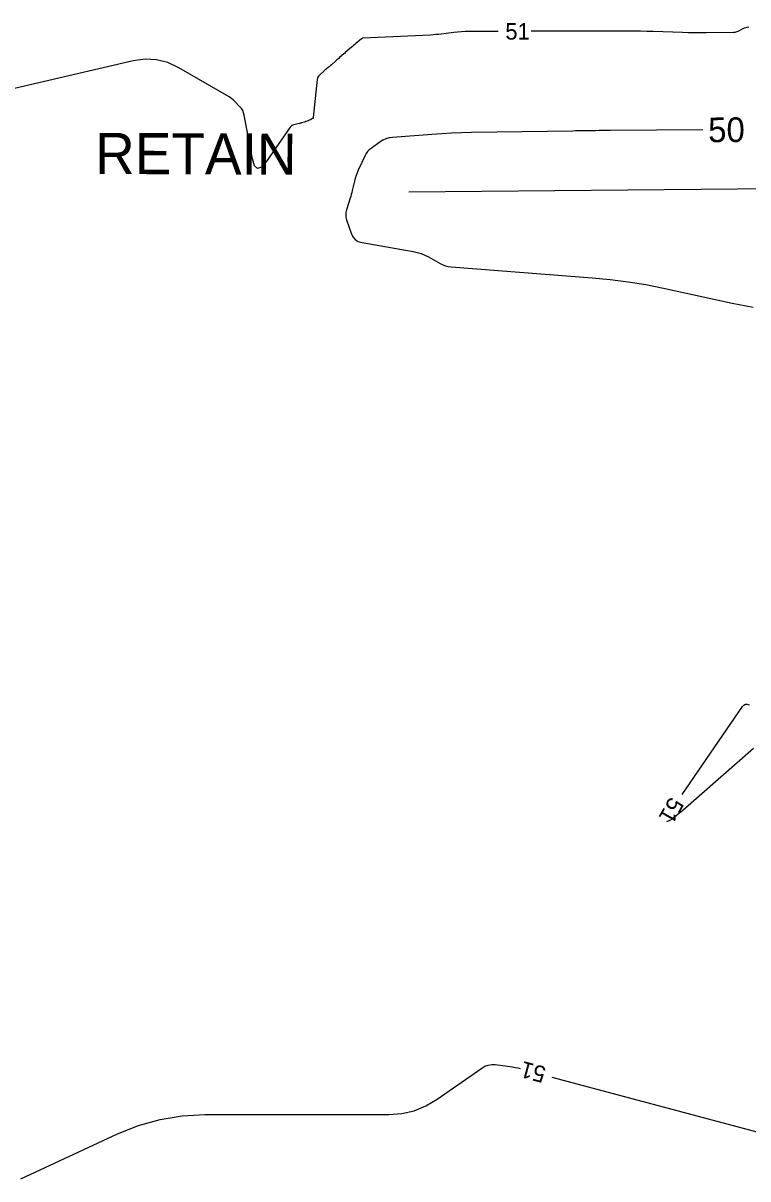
# Model space of a CAD drawing. Extents: x 2384780 to 2405861, y 547869 to 573706.
# Drawn here: x 2391543.5 to 2391631.6, y 552463.3 to 552603.9 of the extents above; entities that cross this region are included whole.
import ezdxf

# ---------------------------------------------------------------- set-up
doc = ezdxf.new("R2010")
doc.units = 0
for name, color, linetype in [('Old_Level_5', 7, 'Continuous'), ('Old_Level_60', 7, 'Continuous'), ('Old_Level_61', 7, 'Continuous')]:
    doc.layers.add(name, color=color, linetype=linetype)

msp = doc.modelspace()

# ---------------------------------------------------------------- linework, layer by layer
at = {"layer": 'Old_Level_5'}
msp.add_line((2391590.4, 552583.40025), (2391754.736, 552584.94575), dxfattribs=at)
at = {"layer": 'Old_Level_60'}
for points in [[(2391631.75, 552603.4255), (2391631.55325, 552603.40975), (2391631.3625, 552603.372), (2391631.17725, 552603.312), (2391630.998, 552603.22975), (2391630.4215, 552602.925), (2391630.296, 552602.86775), (2391630.1665, 552602.8265), (2391630.03275, 552602.801), (2391629.89525, 552602.79175), (2391626.55125, 552602.7595), (2391625.83475, 552602.75625), (2391625.1185, 552602.761), (2391624.40225, 552602.77325), (2391623.686, 552602.79325), (2391620.101, 552602.9125), (2391619.33275, 552602.93475), (2391618.56425, 552602.95025), (2391617.79575, 552602.95875), (2391617.02725, 552602.96075), (2391605.2555, 552602.938)], [(2391601.2555, 552602.93025), (2391597.7095, 552602.9235), (2391597.24275, 552602.915), (2391596.77675, 552602.892), (2391596.312, 552602.854), (2391595.848, 552602.8015), (2391594.33425, 552602.60525), (2391594.0095, 552602.5665), (2391593.68425, 552602.53425), (2391593.35825, 552602.509), (2391593.03175, 552602.49025), (2391584.76875, 552602.10075), (2391584.75225, 552602.09875), (2391584.7365, 552602.09425), (2391584.722, 552602.08725), (2391584.70825, 552602.07775), (2391584.665, 552602.043), (2391584.656, 552602.0355), (2391584.64675, 552602.028), (2391584.6375, 552602.0205), (2391584.62825, 552602.01275), (2391583.94775, 552601.44925), (2391583.80225, 552601.32825), (2391583.657, 552601.20675), (2391583.51225, 552601.0845), (2391583.368, 552600.962), (2391582.89425, 552600.55825), (2391582.793, 552600.4715), (2391582.692, 552600.3845), (2391582.59125, 552600.29725), (2391582.49075, 552600.2095), (2391581.96525, 552599.74875), (2391581.85275, 552599.65), (2391581.74075, 552599.55075), (2391581.62875, 552599.45125), (2391581.51725, 552599.3515), (2391580.9545, 552598.84675), (2391580.871, 552598.7735), (2391580.786, 552598.70225), (2391580.69925, 552598.63325), (2391580.61075, 552598.566), (2391580.31975, 552598.3495), (2391580.258, 552598.3025), (2391580.1975, 552598.2535), (2391580.1385, 552598.20325), (2391580.081, 552598.151), (2391579.5115, 552597.62275), (2391579.4025, 552597.503), (2391579.32, 552597.37), (2391579.26325, 552597.224), (2391579.233, 552597.065), (2391578.75175, 552592.445), (2391578.743, 552592.404), (2391578.72575, 552592.36875), (2391578.7, 552592.33925), (2391578.66575, 552592.31525), (2391578.54, 552592.246), (2391578.51275, 552592.2315), (2391578.4855, 552592.2175), (2391578.45775, 552592.204), (2391578.43, 552592.191), (2391578.2555, 552592.112), (2391578.218, 552592.0955), (2391578.18025, 552592.0795), (2391578.14225, 552592.0645), (2391578.10375, 552592.05), (2391577.878, 552591.96775), (2391577.82925, 552591.9505), (2391577.7805, 552591.934), (2391577.7315, 552591.9185), (2391577.682, 552591.90375), (2391577.334, 552591.803), (2391577.25925, 552591.782), (2391577.18425, 552591.76175), (2391577.109, 552591.74225), (2391577.03375, 552591.724), (2391576.3895, 552591.57075), (2391576.25875, 552591.5275), (2391576.142, 552591.46325), (2391576.03975, 552591.37825), (2391575.9515, 552591.272), (2391573.02975, 552587.069), (2391572.45625, 552586.4155), (2391571.988, 552586.25675), (2391571.625, 552586.5925), (2391571.36725, 552587.42275), (2391570.353, 552592.748), (2391570.2795, 552593.0275), (2391570.1685, 552593.288), (2391570.0205, 552593.52925), (2391569.8355, 552593.751), (2391569.16975, 552594.445), (2391569.02275, 552594.588), (2391568.86675, 552594.71975), (2391568.702, 552594.84025), (2391568.52825, 552594.94925), (2391562.40875, 552598.5055), (2391561.0765, 552599.12925), (2391559.70325, 552599.47625), (2391558.28825, 552599.547), (2391556.83175, 552599.34075)], [(2391556.83175, 552599.34075), (2391542.40275, 552595.97725)], [(2391623.61725, 552510.10775), (2391630.9905, 552520.79975), (2391631.153, 552520.97775), (2391631.3385, 552521.07425), (2391631.547, 552521.08925), (2391631.77875, 552521.0225)], [(2391632.295, 552515.705), (2391623.72075, 552508.162), (2391622.28675, 552506.9995), (2391621.734, 552506.775)], [(2391543.199, 552463.3355), (2391554.95975, 552468.81625), (2391557.5125, 552469.84375), (2391560.13, 552470.57775), (2391562.813, 552471.01825), (2391565.56075, 552471.165), (2391587.9315, 552471.165), (2391589.512, 552471.28075), (2391591.01925, 552471.628), (2391592.454, 552472.20675), (2391593.81575, 552473.017), (2391599.2555, 552476.81725), (2391599.638, 552477.0385), (2391600.04, 552477.1815), (2391600.462, 552477.2465), (2391600.9035, 552477.23325), (2391602.37825, 552477.06225), (2391602.693, 552477.02), (2391603.006, 552476.9665), (2391603.3165, 552476.9015), (2391603.625, 552476.82525), (2391603.908, 552476.74975)], [(2391607.77325, 552475.72), (2391636.52675, 552468.05975)]]:
    msp.add_lwpolyline(points, dxfattribs=at)
at = {"layer": 'Old_Level_61'}
for points in [[(2391626.15625, 552590.94425), (2391614.87375, 552590.872), (2391614.42425, 552590.86875), (2391613.9745, 552590.86425), (2391613.525, 552590.859), (2391613.0755, 552590.8525), (2391611.607, 552590.83025), (2391611.29225, 552590.8255), (2391610.9775, 552590.82075), (2391610.663, 552590.81575), (2391610.34825, 552590.811), (2391597.9985, 552590.6225), (2391596.7925, 552590.59475), (2391595.58725, 552590.5485), (2391594.383, 552590.48325), (2391593.1795, 552590.3995), (2391588.39425, 552590.02875), (2391587.98925, 552589.9705), (2391587.60325, 552589.85975), (2391587.23625, 552589.6965), (2391586.88825, 552589.48125), (2391585.78275, 552588.69175), (2391585.56025, 552588.51075), (2391585.366, 552588.306), (2391585.2005, 552588.0775), (2391585.0635, 552587.8255), (2391584.235, 552586.04575), (2391584.094, 552585.72125), (2391583.96975, 552585.39075), (2391583.8625, 552585.05425), (2391583.77225, 552584.712), (2391583.5055, 552583.584), (2391583.446, 552583.34275), (2391583.38225, 552583.103), (2391583.314, 552582.86425), (2391583.2415, 552582.62675), (2391582.7955, 552581.21525), (2391582.7245, 552580.91325), (2391582.70275, 552580.6115), (2391582.73, 552580.31), (2391582.80675, 552580.00925)], [(2391582.80675, 552580.00925), (2391583.3605, 552578.3645), (2391583.565, 552577.9325), (2391583.854, 552577.59925), (2391584.2275, 552577.365), (2391584.68575, 552577.22925), (2391590.92475, 552576.154), (2391591.411, 552576.049), (2391591.883, 552575.904), (2391592.341, 552575.719), (2391592.78475, 552575.494), (2391594.21075, 552574.69375), (2391594.52175, 552574.54025), (2391594.84375, 552574.423), (2391595.17675, 552574.34175), (2391595.52075, 552574.29675), (2391612.683, 552572.9685), (2391614.87175, 552572.7615), (2391617.0495, 552572.4795), (2391619.21625, 552572.12275), (2391621.372, 552571.69125), (2391629.73675, 552569.867), (2391630.573, 552569.6925), (2391631.412, 552569.5335), (2391632.2535, 552569.39)]]:
    msp.add_lwpolyline(points, dxfattribs=at)

# ---------------------------------------------------------------- texts
at = {"layer": 'Old_Level_5'}
msp.add_text('RETAIN', height=5, rotation=359.7747472, dxfattribs=at).set_placement((2391552.20225, 552585.5855))
at = {"layer": 'Old_Level_60'}
for rotation, p in [(0.1108417, (2391602.1235, 552601.932)), (240.5302778, (2391622.18925, 552509.927)), (165.0820806, (2391607.1935, 552476.9095))]:
    msp.add_text('51', height=2, rotation=rotation, dxfattribs=at).set_placement(p)
at = {"layer": 'Old_Level_61'}
msp.add_text('50', height=3, rotation=0.3667806, dxfattribs=at).set_placement((2391626.80375, 552589.4485))

doc.saveas('drawing.dxf')
